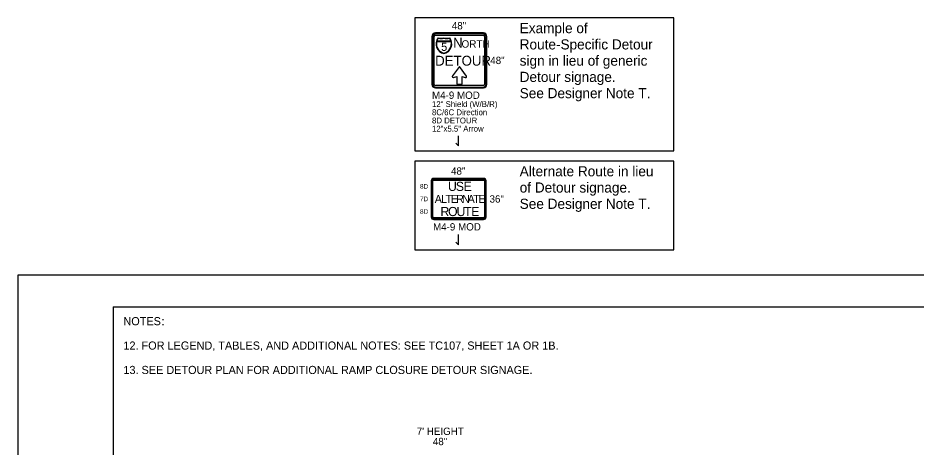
# Model space of a CAD drawing. Extents: x 99999 to 100116, y 99995 to 100013.
# Drawn here: x 100059.06 to 100067.9, y 100009 to 100013.22 of the extents above; entities that cross this region are included whole.
import ezdxf

# ---------------------------------------------------------------- set-up
doc = ezdxf.new("R2010")
doc.units = 0
for name, color, linetype in [('SH_GI_GeneralNotesBodyText', 7, 'Continuous'), ('SH_GI_PlotLimits', 7, 'Continuous'), ('SH_GI_SheetBorder', 7, 'Continuous'), ('TR_SN_ConstructionSigns', 7, 'Continuous'), ('TR_WZ_WorkZoneDetails', 7, 'Continuous')]:
    doc.layers.add(name, color=color, linetype=linetype)

msp = doc.modelspace()

# ---------------------------------------------------------------- linework, layer by layer
at = {"layer": 'SH_GI_PlotLimits'}
msp.add_lwpolyline([(100059.0625, 99999.6875), (100076.0625, 99999.6875), (100076.0625, 100010.6875), (100059.0625, 100010.6875)], close=True, dxfattribs=at)
at = {"layer": 'SH_GI_SheetBorder'}
for q in [(100060, 100000), (100075.75, 100010.375)]:
    msp.add_line((100060, 100010.375), q, dxfattribs=at)
at = {"layer": 'TR_SN_ConstructionSigns'}
for p, q in [((100063.1354, 100013.0373), (100063.1354, 100012.5648)), ((100063.1438, 100013.0373), (100063.1438, 100012.5648)), ((100063.1579, 100012.5648), (100063.1579, 100013.0373)), ((100063.6416, 100013.0711), (100063.1691, 100013.0711)), ((100063.6416, 100013.0626), (100063.1691, 100013.0626)), ((100063.1691, 100013.0486), (100063.6416, 100013.0486)), ((100063.6529, 100013.0373), (100063.6529, 100012.5648)), ((100063.6669, 100012.5648), (100063.6669, 100013.0373)), ((100063.6754, 100012.5648), (100063.6754, 100013.0373)), ((100063.3228, 100012.9875), (100063.1823, 100012.9875)), ((100063.1823, 100012.9875), (100063.3228, 100012.9875)), ((100063.1834, 100012.9912), (100063.3217, 100012.9912)), ((100063.3217, 100012.9912), (100063.1834, 100012.9912)), ((100063.6416, 100012.5536), (100063.1691, 100012.5536)), ((100063.1691, 100012.5395), (100063.6416, 100012.5395)), ((100063.1691, 100012.5311), (100063.6416, 100012.5311)), ((100063.6424, 100011.6405), (100063.153, 100011.6405)), ((100063.6424, 100011.6335), (100063.153, 100011.6335)), ((100063.153, 100011.6236), (100063.6424, 100011.6236)), ((100063.1277, 100011.6152), (100063.1277, 100011.2608)), ((100063.1347, 100011.6152), (100063.1347, 100011.2608)), ((100063.1446, 100011.2608), (100063.1446, 100011.6152)), ((100063.6508, 100011.6152), (100063.6508, 100011.2608)), ((100063.6607, 100011.2608), (100063.6607, 100011.6152)), ((100063.6677, 100011.2608), (100063.6677, 100011.6152)), ((100063.6424, 100011.2524), (100063.153, 100011.2524)), ((100063.153, 100011.2425), (100063.6424, 100011.2425)), ((100063.153, 100011.2355), (100063.6424, 100011.2355))]:
    msp.add_line(p, q, dxfattribs=at)
msp.add_lwpolyline([(100063.3367, 100012.6494), (100063.3356, 100012.6478), (100063.335, 100012.6461), (100063.3347, 100012.6441), (100063.3348, 100012.6424), (100063.335, 100012.6412), (100063.3356, 100012.6398), (100063.3373, 100012.6375), (100063.3386, 100012.6364), (100063.34, 100012.6355), (100063.3417, 100012.6348), (100063.3432, 100012.6345), (100063.3447, 100012.6343), (100063.3465, 100012.6343), (100063.3478, 100012.6346), (100063.3795, 100012.6424), (100063.3795, 100012.5671), (100063.4307, 100012.5671), (100063.4307, 100012.6429), (100063.4617, 100012.6337), (100063.4647, 100012.6331), (100063.4681, 100012.6334), (100063.4703, 100012.6342), (100063.4733, 100012.6362), (100063.4752, 100012.6389), (100063.476, 100012.6414), (100063.4761, 100012.6436), (100063.4754, 100012.6463), (100063.4746, 100012.6477), (100063.4051, 100012.7405), (100063.3367, 100012.6494)], dxfattribs=at)
for centre, radius, start, end in [((100063.1691, 100013.0373), 0.0337, 90, 180), ((100063.1691, 100013.0373), 0.0253, 90, 180), ((100063.1691, 100013.0373), 0.0113, 90, 180), ((100063.6416, 100013.0373), 0.0338, 360, 90), ((100063.6416, 100013.0373), 0.0253, 360, 90), ((100063.6416, 100013.0373), 0.0113, 360, 90), ((100063.2725, 100012.9642), 0.0973, 142.16169, 258.18105), ((100063.2715, 100012.9633), 0.0925, 164.85517, 258.18105), ((100063.2715, 100012.9633), 0.0925, 164.85517, 258.18105), ((100063.2715, 100012.9633), 0.0925, 142.16169, 162.48397), ((100063.2715, 100012.9633), 0.0925, 142.16169, 162.48397), ((100063.2245, 100013.1212), 0.1014, 253.48525, 286.04538), ((100063.2259, 100013.1124), 0.0964, 253.48525, 286.04538), ((100063.2259, 100013.1124), 0.0964, 253.48525, 286.04538), ((100063.2806, 100013.1212), 0.1014, 253.95462, 286.51475), ((100063.2792, 100013.1124), 0.0964, 253.95462, 286.51475), ((100063.2792, 100013.1124), 0.0964, 253.95462, 286.51475), ((100063.2325, 100012.9642), 0.0974, 281.90384, 37.84925), ((100063.2335, 100012.9633), 0.0925, 281.90384, 15.1558), ((100063.2335, 100012.9633), 0.0925, 281.90384, 15.1558), ((100063.2335, 100012.9633), 0.0925, 17.52691, 37.84925), ((100063.2335, 100012.9633), 0.0925, 17.52691, 37.84925), ((100063.1691, 100012.5648), 0.0338, 180, 270), ((100063.1691, 100012.5648), 0.0253, 180, 270), ((100063.1691, 100012.5648), 0.0113, 180, 270), ((100063.6416, 100012.5648), 0.0337, 270, 360), ((100063.6416, 100012.5648), 0.0253, 270, 0), ((100063.6416, 100012.5648), 0.0113, 270, 0), ((100063.153, 100011.6152), 0.0253, 90, 180), ((100063.153, 100011.6152), 0.0183, 90, 180), ((100063.153, 100011.6152), 0.00844, 90, 180), ((100063.6424, 100011.6152), 0.0253, 360, 90), ((100063.6424, 100011.6152), 0.0183, 360, 90), ((100063.6424, 100011.6152), 0.00844, 360, 90), ((100063.153, 100011.2608), 0.0253, 180, 270), ((100063.153, 100011.2608), 0.0183, 180, 270), ((100063.153, 100011.2608), 0.00844, 180, 270), ((100063.6424, 100011.2608), 0.0253, 270, 360), ((100063.6424, 100011.2608), 0.0183, 270, 0), ((100063.6424, 100011.2608), 0.00844, 270, 0)]:
    msp.add_arc(centre, radius, start, end, dxfattribs=at)
at = {"layer": 'TR_WZ_WorkZoneDetails'}
for p, q in [((100063.3963, 100011.9605), (100063.3963, 100012.0605)), ((100063.3713, 100011.9855), (100063.3963, 100011.9605)), ((100063.3963, 100010.9875), (100063.3963, 100011.0875)), ((100063.3713, 100011.0125), (100063.3963, 100010.9875))]:
    msp.add_line(p, q, dxfattribs=at)
for points in [[(100062.9666, 100011.9105), (100065.5143, 100011.9105), (100065.5143, 100013.2191), (100062.9666, 100013.2191)], [(100062.9666, 100010.9375), (100065.5143, 100010.9375), (100065.5143, 100011.8105), (100062.9666, 100011.8105)]]:
    msp.add_lwpolyline(points, close=True, dxfattribs=at)

# ---------------------------------------------------------------- texts
at = {"layer": 'SH_GI_GeneralNotesBodyText'}
for s, p in [('NOTES', (100060.1, 100010.195)), (':', (100060.4743, 100010.195)), ('12. FOR LEGEND, TABLES, AND ADDITIONAL NOTES: SEE TC107, SHEET 1A OR 1B.', (100060.1, 100009.955)), ('13. SEE DETOUR PLAN FOR ADDITIONAL RAMP CLOSURE DETOUR SIGNAGE.', (100060.1, 100009.715))]:
    msp.add_text(s, height=0.08, rotation=360, dxfattribs=at).set_placement(p)
at = {"layer": 'TR_SN_ConstructionSigns'}
for s, height, p in [('48"', 0.072, (100063.3306, 100013.1071)), ('5', 0.081, (100063.2253, 100012.8951)), ('N', 0.0972, (100063.3432, 100012.9267)), ('ORTH', 0.0729, (100063.4264, 100012.9267)), ('DETOUR', 0.0972, (100063.1668, 100012.7497)), ('48"', 0.072, (100063.7086, 100012.7651)), ('M4-9 MOD', 0.072, (100063.1354, 100012.4231)), ('12" Shield (W/B/R)', 0.0576, (100063.1354, 100012.3424)), ('8C/6C Direction', 0.0576, (100063.1354, 100012.2618)), ('8D DETOUR', 0.0576, (100063.1354, 100012.1811)), ('12"x5.5" Arrow', 0.0576, (100063.1354, 100012.1005)), ('48"', 0.072, (100063.323, 100011.6765)), ('36"', 0.072, (100063.7015, 100011.402)), ('M4-9 MOD', 0.072, (100063.1457, 100011.1275)), ("7' HEIGHT", 0.072, (100062.9856, 100009.1157)), ('48"', 0.072, (100063.144, 100009.0149))]:
    msp.add_text(s, height=height, rotation=360, dxfattribs=at).set_placement(p)
for s, height, p in [('8D', 0.045, (100063.018, 100011.5392)), ('U', 0.09, (100063.2933, 100011.5167)), ('S', 0.09, (100063.3698, 100011.5167)), ('E', 0.09, (100063.4463, 100011.5167)), ('7D', 0.045, (100063.018, 100011.4155)), ('A', 0.0787, (100063.1626, 100011.3986)), ('L', 0.0787, (100063.2241, 100011.3986)), ('T', 0.0787, (100063.269, 100011.3986)), ('E', 0.0787, (100063.3201, 100011.3986)), ('R', 0.0787, (100063.3737, 100011.3986)), ('N', 0.0787, (100063.4312, 100011.3986)), ('A', 0.0787, (100063.4863, 100011.3986)), ('T', 0.0787, (100063.5414, 100011.3986)), ('E', 0.0787, (100063.5926, 100011.3986)), ('R', 0.09, (100063.2186, 100011.2692)), ('O', 0.09, (100063.2933, 100011.2692)), ('U', 0.09, (100063.377, 100011.2692)), ('T', 0.09, (100063.4517, 100011.2692)), ('E', 0.09, (100063.521, 100011.2692)), ('8D', 0.045, (100063.018, 100011.2917))]:
    msp.add_text(s, height=height, dxfattribs=at).set_placement(p)
at = {"layer": 'TR_WZ_WorkZoneDetails'}
for s, p in [('Example of ', (100063.9983, 100013.0691)), ('Route-Specific Detour ', (100063.9983, 100012.9091)), ('sign in lieu of generic ', (100063.9983, 100012.7491)), ('Detour signage.', (100063.9983, 100012.5891)), ('See Designer Note T.', (100063.9983, 100012.4291)), ('Alternate Route in lieu ', (100063.9983, 100011.6605)), ('of Detour signage.', (100063.9983, 100011.5005)), ('See Designer Note T.', (100063.9983, 100011.3405))]:
    msp.add_text(s, height=0.1, dxfattribs=at).set_placement(p)

doc.saveas('drawing.dxf')
